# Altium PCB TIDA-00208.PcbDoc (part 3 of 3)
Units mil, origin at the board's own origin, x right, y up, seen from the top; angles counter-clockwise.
Board outline 4724.41 x 3937.01 mil, 4 copper layers (Top Layer, MidLayer1, MidLayer2, Bottom Layer), stack 90 mil thick; 243 components, 132 nets, 667 pads, 234 vias.
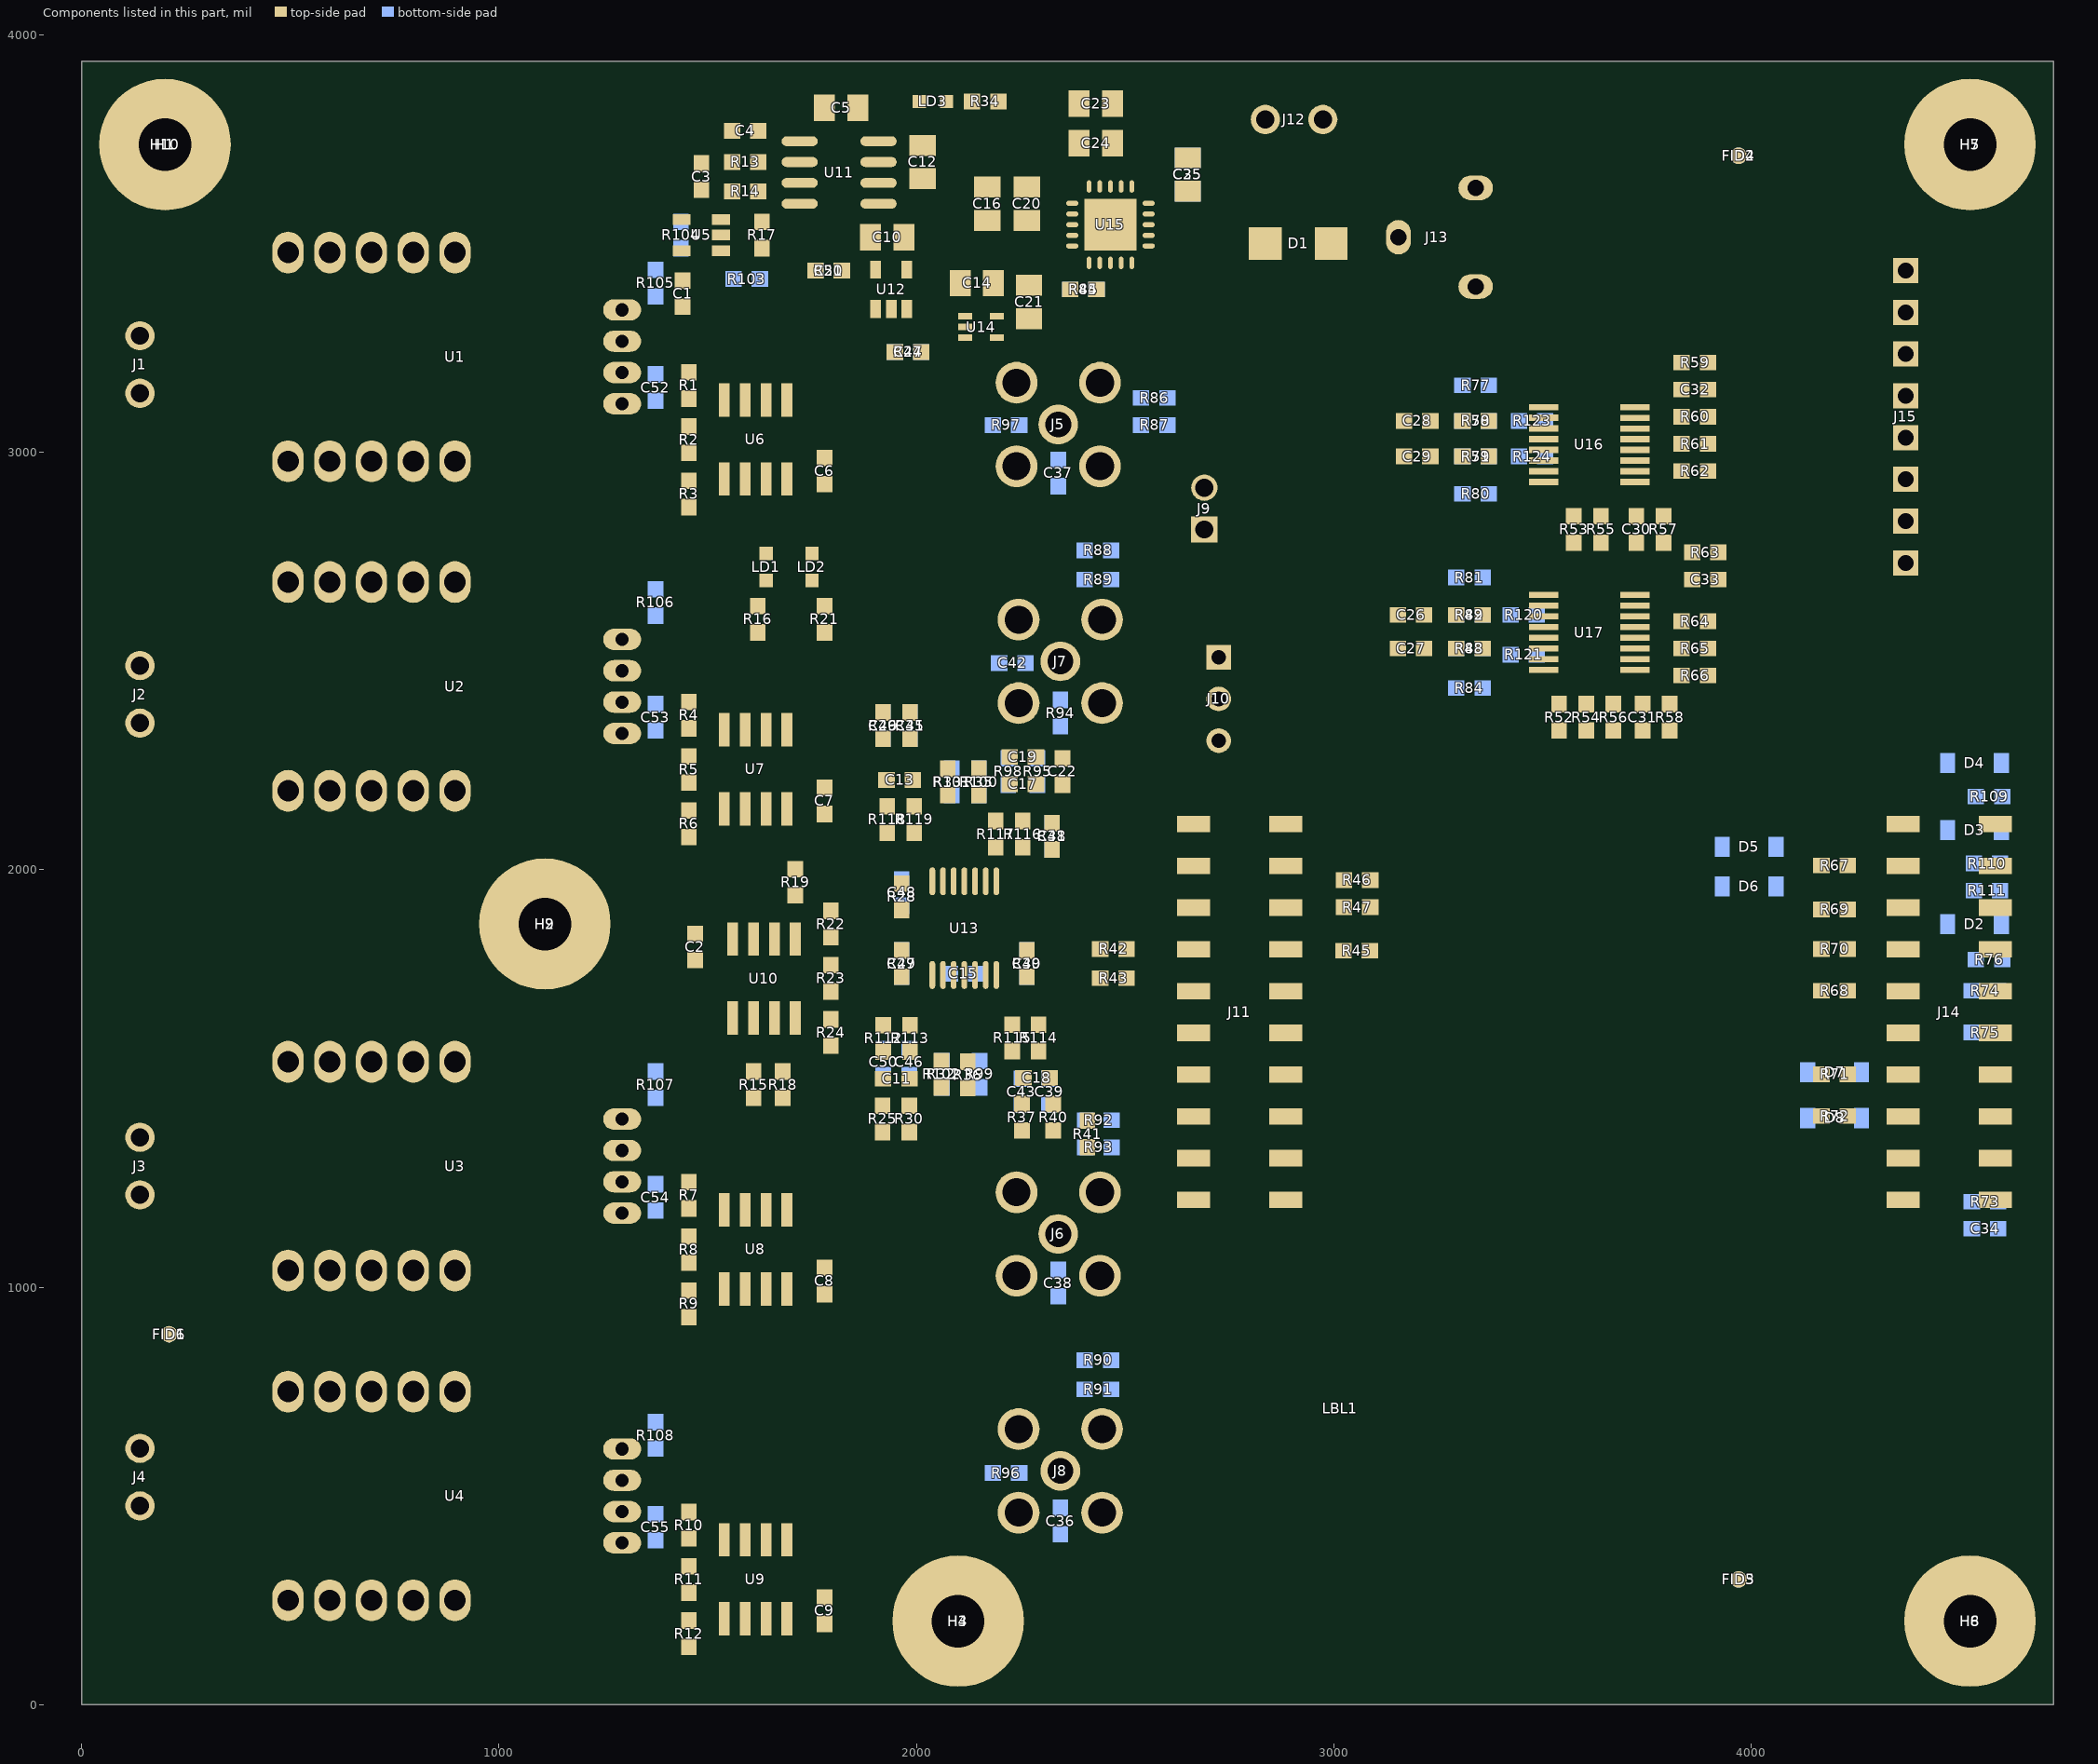
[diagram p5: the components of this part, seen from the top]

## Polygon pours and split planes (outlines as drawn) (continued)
NetJ1_2 on Top Layer "Bottom Layer-No Net" (solid, remove dead copper, pour order 82): 930,2919.37 120,2919.37 80,2959.37 75,2964.37 75,3149.37 75,3152.9 90.55,3168.46 96.47,3174.37 205,3174.37 230,3174.37 290,3114.37 325,3079.37 540,3079.37 910,3079.37 945,3044.37 950,3039.37 950,2954.37 950,2934.37 940,2924.37 935,2919.37 930,2919.37
NetJ1_1 on Top Layer "Bottom Layer-No Net" (solid, remove dead copper, pour order 66): 935,3509.37 935,3444.37 915,3424.37 855,3364.37 670,3364.37 330,3364.37 210,3244.37 205,3239.37 85,3239.37 65,3259.37 65,3309.37 65,3494.37 100,3529.37 105,3534.37 490,3534.37 925,3534.37 930,3529.37 935,3524.37 935,3509.37
NetJ2_1 on Top Layer "Bottom Layer-No Net" (solid, remove dead copper, pour order 70): 935,2720 935,2655 915,2635 855,2575 670,2575 330,2575 210,2455 205,2450 85,2450 65,2470 65,2520 65,2705 100,2740 105,2745 490,2745 925,2745 930,2740 935,2735 935,2720
NetJ2_2 on Top Layer "Bottom Layer-No Net" (solid, remove dead copper, pour order 86): 930,2130 120,2130 80,2170 75,2175 75,2360 75,2363.53 90.55,2379.09 96.47,2385 205,2385 230,2385 290,2325 325,2290 540,2290 910,2290 945,2255 950,2250 950,2165 950,2145 940,2135 935,2130 930,2130
NetD1_2 on Top Layer "Bottom Layer-No Net" (solid, remove dead copper, pour order 87): 3415,3350 2965,3350 2935,3380 2935,3855 2945,3865 3055,3865 3095,3825 3095,3470 3110,3455 3420,3455 3435,3440 3435,3370
NetC25_1 on Top Layer "Bottom Layer-No Net" (solid, remove dead copper, pour order 88): 2875,3410 2875,3615 2840,3650 2600,3650 2570,3680 2520,3680 2515,3675 2515,3630 2545,3630 2555,3620 2556.54,3545 2575,3545 2590,3530 2615,3530 2750,3395 2860,3395
GND on Top Layer "Bottom Layer-No Net" (solid, remove dead copper, pour order 90): 2595,3680 2720,3680 2840,3680 2880,3720 2885,3725 2885,3855 2875,3865 2785,3865 2595,3865 2580,3850 2580,3760 2580,3695 2595,3680
3V3 on Top Layer "Bottom Layer-No Net" (solid, remove dead copper, pour order 93): 2190,3350 2390,3350 2410,3330 2410,3265 2400,3255 2275,3255 2220,3310 2190,3310 2188.8,3311.2 2188.8,3348.8
AVDD on Top Layer "Bottom Layer-No Net" (solid, remove dead copper, pour order 91): 2330,3590 2310,3610 2100,3610 2085,3595 2085,3505 2135,3455 2135,3325 1965,3325 1965,3460 1945,3480 1945,3535 1975,3565 1975,3621 1970,3630 1880,3630 1880,3660 1960,3660 1985,3685 2075,3685 2085,3695 2085,3775 2090,3780 2165,3780 2185,3800 2185,3865 2195,3875 2410,3875 2415,3870 2415,3680 2385,3650 2385,3590
GND on Bottom Layer "Bottom Layer-No Net" (solid, remove dead copper, pour order 53): 3965,1925 3965,2070 3950,2085 3780,2085 3765,2070 3765,1925 3772,1918 3958,1918
GND on Bottom Layer "Bottom Layer-No Net 1" (solid, pour order 50): 4346,2331 4309,2294 4309,1911 4380,1840 4487,1840 4492,1845 4492,1895 4485,1902 4463,1902 4440,1925 4440,2041 4460,2061 4485,2061 4493,2069 4493,2121 4487,2127 4459,2127 4436,2150 4436,2202 4457,2223 4486,2223 4494,2231 4494,2305 4468,2331
GND on Bottom Layer "Bottom Layer-No Net" (solid, remove dead copper, pour order 59): 2360,3475 2520,3475 2535,3490 2535,3605 2610,3680 2610,3865 2375,3865 2360,3850
NetJ4_2 on Bottom Layer "Bottom Layer-No Net" (solid, remove dead copper, pour order 76): 120,191.02 75,236.02 75,450 75,500 90,515 185,515 350,350 910,351.02 950,311.02 950,206.02 935,191.02
NetJ4_1 on Bottom Layer "Bottom Layer-No Net" (solid, remove dead copper, pour order 48): 935,685 920,670 380,670 290,580 75,580 65,590 65,766.02 105,806.02 925,806.02 935,796.02
GND on Bottom Layer "Bottom Layer-No Net" (solid, remove dead copper, pour order 89): 2595,3680 2720,3680 2840,3680 2880,3720 2885,3725 2885,3855 2875,3865 2785,3865 2595,3865 2580,3850 2580,3760 2580,3695 2595,3680
NetJ3_2 on Bottom Layer "Bottom Layer-No Net" (solid, remove dead copper, pour order 73): 120,981.02 75,1026.02 75,1240 95,1260 210,1260 325,1141.02 910,1141.02 950,1101.02 950,996.02 935,981.02
NetJ3_1 on Bottom Layer "Bottom Layer-No Net" (solid, remove dead copper, pour order 61): 935,1506.02 855,1426.02 330,1426.02 225,1320 85,1320 65,1340 65,1556.02 105,1596.02 925,1596.02 935,1586.02
NetJ1_2 on Bottom Layer "Bottom Layer-No Net" (solid, remove dead copper, pour order 81): 930,2919.37 120,2919.37 80,2959.37 75,2964.37 75,3149.37 75,3152.9 90.55,3168.46 96.47,3174.37 205,3174.37 230,3174.37 290,3114.37 325,3079.37 540,3079.37 910,3079.37 945,3044.37 950,3039.37 950,2954.37 950,2934.37 940,2924.37 935,2919.37 930,2919.37
NetJ1_1 on Bottom Layer "Bottom Layer-No Net" (solid, remove dead copper, pour order 65): 935,3509.37 935,3444.37 915,3424.37 855,3364.37 670,3364.37 330,3364.37 210,3244.37 205,3239.37 85,3239.37 65,3259.37 65,3309.37 65,3494.37 100,3529.37 105,3534.37 490,3534.37 925,3534.37 930,3529.37 935,3524.37 935,3509.37
NetJ2_1 on Bottom Layer "Bottom Layer-No Net" (solid, remove dead copper, pour order 69): 935,2720 935,2655 915,2635 855,2575 670,2575 330,2575 210,2455 205,2450 85,2450 65,2470 65,2520 65,2705 100,2740 105,2745 490,2745 925,2745 930,2740 935,2735 935,2720
NetJ2_2 on Bottom Layer "Bottom Layer-No Net" (solid, remove dead copper, pour order 85): 930,2130 120,2130 80,2170 75,2175 75,2360 75,2363.53 90.55,2379.09 96.47,2385 205,2385 230,2385 290,2325 325,2290 540,2290 910,2290 945,2255 950,2250 950,2165 950,2145 940,2135 935,2130 930,2130
GND on Bottom Layer "Bottom Layer-No Net" (solid, remove dead copper, pour order 55): 4240,1570 4240,1310 4240,1255 4255,1240 4335,1240 4340,1240 4350,1250 4355,1255 4355,1445 4355,1560 4340,1575 4330,1585 4260,1585 4255,1585 4240,1570
NetJ4_2 on MidLayer1 "Bottom Layer-No Net" (solid, remove dead copper, pour order 75): 120,191.02 75,236.02 75,450 75,500 90,515 185,515 350,350 910,351.02 950,311.02 950,206.02 935,191.02
NetJ4_1 on MidLayer1 "Bottom Layer-No Net" (solid, remove dead copper, pour order 52): 935,685 920,670 380,670 290,580 75,580 65,590 65,766.02 105,806.02 925,806.02 935,796.02
NetJ3_2 on MidLayer1 "Bottom Layer-No Net" (solid, remove dead copper, pour order 72): 120,981.02 75,1026.02 75,1240 95,1260 210,1260 325,1141.02 910,1141.02 950,1101.02 950,996.02 935,981.02
NetJ3_1 on MidLayer1 "Bottom Layer-No Net" (solid, remove dead copper, pour order 58): 935,1506.02 855,1426.02 330,1426.02 225,1320 85,1320 65,1340 65,1556.02 105,1596.02 925,1596.02 935,1586.02
NetJ1_2 on MidLayer1 "Bottom Layer-No Net" (solid, remove dead copper, pour order 80): 930,2919.37 120,2919.37 80,2959.37 75,2964.37 75,3149.37 75,3152.9 90.55,3168.46 96.47,3174.37 205,3174.37 230,3174.37 290,3114.37 325,3079.37 540,3079.37 910,3079.37 945,3044.37 950,3039.37 950,2954.37 950,2934.37 940,2924.37 935,2919.37 930,2919.37
NetJ1_1 on MidLayer1 "Bottom Layer-No Net" (solid, remove dead copper, pour order 64): 935,3509.37 935,3444.37 915,3424.37 855,3364.37 670,3364.37 330,3364.37 210,3244.37 205,3239.37 85,3239.37 65,3259.37 65,3309.37 65,3494.37 100,3529.37 105,3534.37 490,3534.37 925,3534.37 930,3529.37 935,3524.37 935,3509.37
NetJ2_1 on MidLayer1 "Bottom Layer-No Net" (solid, remove dead copper, pour order 68): 935,2720 935,2655 915,2635 855,2575 670,2575 330,2575 210,2455 205,2450 85,2450 65,2470 65,2520 65,2705 100,2740 105,2745 490,2745 925,2745 930,2740 935,2735 935,2720
NetJ2_2 on MidLayer1 "Bottom Layer-No Net" (solid, remove dead copper, pour order 84): 930,2130 120,2130 80,2170 75,2175 75,2360 75,2363.53 90.55,2379.09 96.47,2385 205,2385 230,2385 290,2325 325,2290 540,2290 910,2290 945,2255 950,2250 950,2165 950,2145 940,2135 935,2130 930,2130
GND on MidLayer1 "MidLayer1-GND" (solid, remove dead copper, pour order 92): 1250,55 1250,3855 1276.89,3881.89 4660,3881.89 4680,3855 4680,75 4670,55.12 4479.88,55
NetJ4_2 on MidLayer2 "Bottom Layer-No Net" (solid, remove dead copper, pour order 74): 120,191.02 75,236.02 75,450 75,500 90,515 185,515 350,350 910,351.02 950,311.02 950,206.02 935,191.02
NetJ4_1 on MidLayer2 "Bottom Layer-No Net" (solid, remove dead copper, pour order 51): 935,685 920,670 380,670 290,580 75,580 65,590 65,766.02 105,806.02 925,806.02 935,796.02
NetJ3_2 on MidLayer2 "Bottom Layer-No Net" (solid, remove dead copper, pour order 71): 120,981.02 75,1026.02 75,1240 95,1260 210,1260 325,1141.02 910,1141.02 950,1101.02 950,996.02 935,981.02
NetJ3_1 on MidLayer2 "Bottom Layer-No Net" (solid, remove dead copper, pour order 57): 935,1506.02 855,1426.02 330,1426.02 225,1320 85,1320 65,1340 65,1556.02 105,1596.02 925,1596.02 935,1586.02
NetJ1_2 on MidLayer2 "Bottom Layer-No Net" (solid, remove dead copper, pour order 79): 930,2919.37 120,2919.37 80,2959.37 75,2964.37 75,3149.37 75,3152.9 90.55,3168.46 96.47,3174.37 205,3174.37 230,3174.37 290,3114.37 325,3079.37 540,3079.37 910,3079.37 945,3044.37 950,3039.37 950,2954.37 950,2934.37 940,2924.37 935,2919.37 930,2919.37
NetJ1_1 on MidLayer2 "Bottom Layer-No Net" (solid, remove dead copper, pour order 63): 935,3509.37 935,3444.37 915,3424.37 855,3364.37 670,3364.37 330,3364.37 210,3244.37 205,3239.37 85,3239.37 65,3259.37 65,3309.37 65,3494.37 100,3529.37 105,3534.37 490,3534.37 925,3534.37 930,3529.37 935,3524.37 935,3509.37
NetJ2_1 on MidLayer2 "Bottom Layer-No Net" (solid, remove dead copper, pour order 67): 935,2720 935,2655 915,2635 855,2575 670,2575 330,2575 210,2455 205,2450 85,2450 65,2470 65,2520 65,2705 100,2740 105,2745 490,2745 925,2745 930,2740 935,2735 935,2720
NetJ2_2 on MidLayer2 "Bottom Layer-No Net" (solid, remove dead copper, pour order 83): 930,2130 120,2130 80,2170 75,2175 75,2360 75,2363.53 90.55,2379.09 96.47,2385 205,2385 230,2385 290,2325 325,2290 540,2290 910,2290 945,2255 950,2250 950,2165 950,2145 940,2135 935,2130 930,2130
AVDD on MidLayer2 "Bottom Layer-No Net" (solid, remove dead copper, pour order 54): 2660,3875 3240,3295 3720,3295 3920,3495 4665,3495 4685,3475 4685,1065 4670,1050 4525,1050 4515,1070 4515,2030 4175,2370 3890,2370 3860,2400 3860,2610 3895,2645 3895,2860 3820,2935 2975,2935 2810,2770 2640,2770 2625,2785 2625,3285 2540,3370 2135,3370 1905,3140 1905,2745 1800,2640 1530,2640 1500,2610 1500,2535 1525,2510 1895,2510 2015,2630 2015,3045 2195,3225 2470,3225 2505,3190 2490,3025 2485,2930 2485,2515 2555,2445 2750,2445 2765,2460 2795,2460 3045,2710 3635,2710 3685,2660 3685,2260 3730,2215 4050,2215 4325,1935 4325,65 1300,65 1250,65.31 1250,3830 1295,3875
3V3 on MidLayer2 "Bottom Layer-No Net" (solid, remove dead copper, pour order 49): 2540,3355 2605,3290 2605,2745 2620,2730 2840,2730 2975,2865 3840,2865 3875,2830 3875,2655 3840,2620 3840,2360 3870,2330 4150,2330 4445,2035 4445,1260 4475,1230 4475,1105 4465,1095 4395,1095 4365,1125 4365,1935 4065,2235 3745,2235 3702.63,2277.37 3702.63,2672.37 3655,2720 3040,2720 2800,2480 2565,2480 2515,2530 2515,3200 2465,3250 2205,3250 2005,3050 2005,2650 1895,2540 1545,2540 1535,2550 1535,2610 1545,2620 1830,2620 1915,2705 1915,3110 2160,3355

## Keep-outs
Keep-Out Layer:
  circle w8: c200,3737.01 r178
  circle w8: c4524.41,3737.01 r178
  circle w8: c4524.41,200 r178
  circle w8: c2100,200 r178
  circle w8: c1110,1870.08 r190.6
  lines w4: 55.12,55.12 55.12,3881.89 4687.2,3881.89 4687.2,55.12 55.12,55.12
  text ".Layer_Name" at 372.2,-1342.12 h60

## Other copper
Top Layer:
  region net AVDD: 2415,3710 2365,3710 2360,3705 2360,3610 2370,3600 2370.49,3600.49 2380,3600.49 2380,3620 2390,3630 2415,3630
  region net NetC25_1: 2519.51,3664.51 2515,3660 2515,3630 2570,3630 2575,3635 2575,3660 2585,3664.51
  text "1" at 3561,89 h100
  text ".Layer_Name" at 372.2,-1342.12 h60
MidLayer1:
  pour cut-out: 1336.81,3386.54 1355,3368.35 1355,3243.35 1340,3228.35 1245,3228.35 1230,3243.35 1230,3383.35 1235,3388.35 1236.81,3386.54
  pour cut-out: 1240,3153.35 1345,3153.35 1360,3138.35 1360,3083.35 1350,3073.35 1240,3073.35 1235,3078.35 1235,3148.35
  pour cut-out: 1336.81,2597.17 1355,2578.98 1355,2453.98 1340,2438.98 1245,2438.98 1230,2453.98 1230,2593.98 1235,2598.98 1236.81,2597.17
  pour cut-out: 1240,2363.98 1345,2363.98 1360,2348.98 1360,2293.98 1350,2283.98 1240,2283.98 1235,2288.98 1235,2358.98
  pour cut-out: 1336.81,1448.19 1355,1430 1355,1305 1340,1290 1245,1290 1230,1305 1230,1445 1235,1450 1236.81,1448.19
  pour cut-out: 1240,1215 1345,1215 1360,1200 1360,1145 1350,1135 1240,1135 1235,1140 1235,1210
  pour cut-out: 1240,425 1345,425 1360,410 1360,355 1350,345 1240,345 1235,350 1235,420
  pour cut-out: 1336.81,658.19 1355,640 1355,515 1340,500 1245,500 1230,515 1230,655 1235,660 1236.81,658.19
  pour cut-out: 3500,65.31 3965,65.31 3965,185 3950,200 3510,200 3500,190
  text "2" at 3659,89 h100
  text ".Layer_Name" at 380,-1340 h60
MidLayer2:
  pour cut-out: 1250,646.38 1344.64,646.38 1355,636.02 1355,441.02 1335,421.02 1250,421.02 1245,426.02 1245,641.38
  pour cut-out: 1250,1436.38 1344.64,1436.38 1355,1426.02 1355,1231.02 1335,1211.02 1250,1211.02 1245,1216.02 1245,1431.38
  pour cut-out: 1250,3374.73 1344.64,3374.73 1355,3364.37 1355,3169.37 1335,3149.37 1250,3149.37 1245,3154.37 1245,3369.73
  pour cut-out: 1250,2585.36 1344.64,2585.36 1355,2575 1355,2380 1335,2360 1250,2360 1245,2365 1245,2580.36
  pour cut-out: 3500,65.31 3965,65.31 3965,185 3950,200 3510,200 3500,190
  text "3" at 3759,89 h100
  text ".Layer_Name" at 380,-1340 h60
Bottom Layer:
  text "4" at 3903,89 h100
  text ".Layer_Name" at 372.2,-1342.12 h60

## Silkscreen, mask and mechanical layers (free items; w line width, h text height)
Top Overlay:
  circle w8: c2330,3610 r10
  circle w8: c2076.37,3327 r10.63
  circle w8: c1901.19,3292.77 r10.63
  circle w8: c1982.23,3592.59 r10.63
  circle w8: c1530.83,3441.37 r10.63
  circle w8: c2340,3066.38 r160.34
  circle w8: c2345,2498.98 r159.39
  circle w8: c2340,1127.4 r161.48
  circle w8: c2345,560 r160
  lines w6: 1510,3752 1510,3742 1529.73,3722.27 1530.02,3722.27 ; 1886,1664 1887,1664 1893.8,1657.2 1893.8,1655.98 ; 2024,2126 2033,2126 2043,2116 ; 2133,2321 2138,2316 2138,2272 ; 2217.2,2025.02 2217.2,1964.8 2238,1944 ; 2314.98,2177.8 2314.98,2165.02 2323,2157 2386,2157 ; 2355.2,1466.98 2380.02,1466.98 2388,1459
  lines w7.87: 1383.16,3589 1521.22,3589 1530.02,3597.8 ; 1500,450 1500,151 1521,151 ; 1500,1240 1500,941 1521,941 ; 1500,2390 1500,2091 1521,2091 ; 1500,3180 1500,2881 1521,2881 ; 1560,151 1730,151 1730,450 1561,450 ; 1560,941 1730,941 1730,1240 1561,1240 ; 1560,2091 1730,2091 1730,2390 1561,2390 ; 1560,2881 1730,2881 1730,3180 1561,3180 ; 1689,1590 1520,1590 1520,1889 1690,1889 ; 1729,1889 1750,1889 1750,1590 ; 3295,2781 3306,2770 3535,2770 ; 3450.1,2449.6 3450.1,2688.1 3768,2688.1 3768,2450.2 3450.7,2450.2 ; 3450.1,2899.6 3450.1,3138.1 3767.2,3138.1 3767.2,2899.8 3450.3,2899.8 ; 3535,2770 3534,2770 3525,2761 3525,2780 3535,2770 ; 2609.41,1109.05 2939.41,1109.05 2939.41,2209.05 2609.41,2209.05 2609.41,1109.05 ; 4309.41,1109.05 4639.41,1109.05 4639.41,2209.05 4309.41,2209.05 4309.41,1109.05 ; 4320,2685 4320,3485 4420,3485 4420,2685 4320,2685
  text "+6V" at 3114,3783 h60 r90
  text "GND" at 2736,3779 h60 r90
  text "GND" at 4195,3410 h55
  text "SDI" at 4215,3315 h55
  text "/CS" at 4220,3215 h55
  text "SCLK" at 4180,3125 h55
  text "SDO_B2" at 4115,3020 h55
  text "GND_FLT" at 2710,3005 h55
  text "SDO_A2" at 4110,2915 h55
  text "SDO_B1" at 4120,2815 h55
  text "SDO_A1" at 4115,2705 h55
  text "OC_FLT" at 2720,2675 h55
  text "2" at 4652.2,2125 h55
  text "1" at 4270.2,2104 h55
  text "1" at 2575.35,2093 h55
  text "2" at 2955.35,2093 h55
  text "19" at 4243.2,1186 h55
  text "20" at 2955.35,1184 h55
  text "20" at 4651.2,1159 h55
  text "19" at 2545.35,1144 h55
  text "TIDA-00208" at 2625,215 h150
  text "REV: E2" at 2650,75 h150
  text ".Layer_Name" at 372.2,-1342.12 h60
Bottom Overlay:
  text ".Layer_Name" at 372.2,-1342.12 h60
Top Paste:
  text ".Layer_Name" at 372.2,-1342.12 h60
Bottom Paste:
  text ".Layer_Name" at 372.2,-1342.12 h60
Top Solder:
  text ".Layer_Name" at 372.2,-1342.12 h60
  text ".Layer_Name" at 372.2,-1342.12 h60
Bottom Solder:
  text ".Layer_Name" at 372.2,-1342.12 h60
Drill Guide:
  text ".Layer_Name" at 372.2,-1342.12 h60
M1 Board Outline:
  the board outline again, w10
  text ".layer_Name" at 392,-1342 h60
M2 Board Dimensions:
  rectangle: -80.3,-894.12 294.7,-769.12
  rectangle: -205.3,-769.12 -80.3,-644.12
  lines w7: -205.3,-769.12 794.7,-769.12 ; -80.3,-894.12 -80.3,-644.12 ; 44.7,-894.12 44.7,-644.12 ; 294.7,-894.12 294.7,-644.12 ; 544.7,-894.12 544.7,-644.12 ; -205.3,-894.12 -205.3,-644.12 794.7,-644.12 794.7,-894.12 -205.3,-894.12
  lines w10: -205.3,-959.12 -205.3,-939.12 ; -145.3,-969.12 -205.3,-949.12 ; -145.3,-929.12 -205.3,-949.12 ; 18.78,-949.12 -205.3,-949.12 ; 570.61,-949.12 794.7,-949.12 ; 734.7,-969.12 794.7,-949.12 ; 734.7,-929.12 794.7,-949.12 ; 794.7,-959.12 794.7,-939.12
  text "1000 (mil)" at 28.78,-985.11 h60
M3 3D STEP Top:
  text ".Layer_Name" at 372.2,-1342.12 h60
M4 3D STEP Bottom:
  text ".Layer_Name" at 372.2,-1342.12 h60
M5 Assembly Top:
  circle w6: c1496,3483 r8
  circle w6: c1866.35,3343.16 r8
  circle w6: c2080,3328 r8
  lines w7.87: 1617,2833 1667,2833 ; 1641,2782 1641,2807 ; 1641,2854 1641,2833 ; 1727,2833 1777,2833 ; 1751,2782 1751,2807 ; 1751,2854 1751,2833 ; 2007,3890 2028,3890 ; 2026,3864 2026,3914 ; 2053,3890 2078,3890 ; 1641,2833 1666,2808 1616,2808 1641,2833 ; 1751,2833 1726,2808 1776,2808 1751,2833 ; 2028,3890 2053,3915 2053,3865 2028,3890
  lines w10: -496.8,-1413.79 6103.2,-1413.79 ; -496.8,-1210.46 6105.2,-1210.46 ; -496.8,-1007.12 -496.8,-1617.12 3508.2,-1617.12 6105.2,-1617.12 6105.2,-1007.12 -496.3,-1007.12 -496.3,-1617.12 1079.2,-1617.12 ; 1968.2,-1617.12 1968.2,-1007.12 ; 3235.2,-1210.46 3235.2,-1007.12 ; 4075.2,-1210.46 4075.2,-1007.12 ; 4697.2,-1623.62 4697.2,-1420.79
  text "8" at 4279,3418 h60
  text "14" at 1173,3094 h60
  text "1" at 885,3063 h60
  text "1" at 4285,2707 h60
  text "14" at 1168,2311 h60
  text "1" at 881,2262 h60
  text "14" at 1174,1158 h60
  text "1" at 882,1112 h60
  text "14" at 1172,368 h60
  text "1" at 879,321 h60
  text "COMPONENTS MARKED 'DNP' SHOULD NOT BE POPULATED." at 948.7,-802.12 h60
  text "ASSEMBLY VARIANT:" at 948.2,-917.62 h60
  text ".VariantName" at 1984.2,-917.62 h60
  text "PCB VIEWED FROM TOP SIDE" at -433.3,-1139.29 h60
  text "BOARD #:" at 2043.2,-1139.29 h60
  text ".PRJ_Number" at 2588.7,-1139.29 h60
  text "REV:" at 3433.2,-1139.29 h60
  text ".PCB_Rev" at 3724.7,-1139.29 h60
  text "SVN REV:" at 4271.2,-1139.29 h60
  text ".VersionControl_RevNumber" at 4777.2,-1139.29 h60
  text "IGNORE ->" at -433.3,-1342.12 h60
  text ".layer_Name" at 392,-1342 h60
  text "PLOT NAME =" at -433.3,-1547.96 h60
  text ".plot_File_Name" at 372.2,-1547.96 h60
  text "GENERATED    :" at 2045.2,-1547.96 h60
  text ".Print_Date" at 2914.7,-1547.96 h60
  text ".Print_Time" at 3643.7,-1547.96 h60
  text "TEXAS INSTRUMENTS" at 4908.2,-1547.96 h60
M6 Assembly Bottom:
  lines w10: -497.3,-1210.96 6104.7,-1210.96 ; -495.3,-1414.29 6104.7,-1414.29 ; 910.7,-1624.12 910.7,-1421.29 ; 1532.7,-1210.96 1532.7,-1007.62 ; 2372.7,-1210.96 2372.7,-1007.62 ; 3639.7,-1617.62 3639.7,-1007.62 ; 4528.7,-1617.62 6104.2,-1617.62 6104.2,-1007.62 -497.3,-1007.62 -497.3,-1617.62 2099.7,-1617.62 6104.7,-1617.62 6104.7,-1007.62
  text "COMPONENTS MARKED 'DNP' SHOULD NOT BE POPULATED." at 5897.2,-801.62 h60
  text ".VariantName" at 4853.2,-917.62 h60
  text "ASSEMBLY VARIANT:" at 5892.2,-917.62 h60
  text ".VersionControl_RevNumber" at 830.7,-1139.79 h60
  text "SVN REV:" at 1336.7,-1139.79 h60
  text ".PCB_Rev" at 1883.2,-1139.79 h60
  text "REV:" at 2174.7,-1139.79 h60
  text ".PRJ_Number" at 3019.2,-1139.79 h60
  text "BOARD #:" at 3564.7,-1139.79 h60
  text "PCB VIEWED FROM BOTTOM SIDE" at 6041.2,-1139.79 h60
  text "IGNORE ->" at 2343.05,-1342.12 h60
  text ".layer_Name" at 1266,-1343 h60
  text "TEXAS INSTRUMENTS" at 699.7,-1548.46 h60
  text ".Print_Time" at 1964.2,-1548.46 h60
  text ".Print_Date" at 2693.2,-1548.46 h60
  text "GENERATED    :" at 3562.7,-1548.46 h60
  text ".plot_File_Name" at 5235.7,-1548.46 h60
  text "PLOT NAME =" at 6041.2,-1548.46 h60
M9 Title Sheet:
  drawing of 57 lines, arcs and shapes, not listed
  text "1" at 535.03,7552.88 h70
  text "2" at 3030.7,7552.88 h70
  text "3" at 5520.04,7552.88 h70
  text "4" at 8026.71,7552.88 h70
  text "5" at 10525.7,7552.88 h70
  text "6" at 13030.7,7552.88 h70
  text "A" at -621.3,6409.88 h70
  text "A" at 14178.7,6409.88 h70
  text "B" at -621.3,4029.88 h70
  text "B" at 14178.7,4029.88 h70
  text "C" at -621.3,1654.88 h70
  text "C" at 14178.7,1654.88 h70
  text "PROJECT TITLE" at 11138.7,-206.12 h35
  text ".PRJ_Title" at 11188.7,-339.45 h55
  text "DESIGNED FOR:" at 11138.7,-507.12 h45
  text ".PRJ_Customer" at 11188.7,-647.12 h70
  text "D" at -621.3,-715.12 h70
  text "D" at 14178.7,-715.12 h70
  text "FILE NAME:" at 11138.7,-807.12 h45
  text ".PCB_File_Name_No_Path" at 11188.7,-927.12 h70
  text "Texas Instruments (TI) and/or its licensors do not warrant the accuracy or completeness of this specification" at 6169.2,-1088.96 h45
  text "ENGINEER:" at 11138.7,-1097.12 h45
  text "LAYOUT BY:" at 12643.7,-1097.12 h45
  text "or any information contained therein. TI and/or its licensors do not warrant that this design will meet" at 6124.21,-1201.63 h45
  text ".PRJ_Engineer" at 11188.7,-1252.11 h70
  text ".PCB_Layout" at 12694.2,-1252.11 h70
  text "the specifications, will be suitable for your application or fit for any particular purpose, or will operate in" at 6124.21,-1314.29 h45
  text "ALTIUM DESIGNER VERSION:" at 12643.7,-1407.12 h45
  text "an implementation. TI and/or its licensors do not warrant that the design is production worthy. You should" at 6124.21,-1426.96 h45
  text "completely validate and test your design implementation to confirm the system functionality for your application." at 6169.2,-1539.62 h45
  text ".print_Scale" at 11188.7,-1540.45 h70
  text ".Application_BuildNumber" at 12694.2,-1540.45 h70
  text "1" at 535.03,-1747.12 h70
  text "2" at 3030.7,-1747.12 h70
  text "3" at 5520.04,-1747.12 h70
  text "4" at 8026.71,-1747.12 h70
  text "5" at 10525.7,-1747.12 h70
  text "6" at 13030.7,-1747.12 h70
M10 Fab Notes:
  drawing of 220 lines, arcs and shapes, not listed
  text "DESIGN INFORMATION" at 12176.21,6326.38 h60
  text "(REFER ALSO ARRAY/PANEL PROFILING INFORMATION)" at 11814.66,6164.66 h60
  text "BOARD SIZE" at 11128.66,6160.38 h60
  text "120 MM" at 11590.98,6032.56 h60
  text "X" at 12096.66,6032.56 h60
  text "100 MM" at 12327.98,6032.56 h60
  text "Number of Layers :" at 11531.66,5835.38 h60
  text "4" at 12626.47,5825.38 h60
  text "MIN. TRACK WIDTH:" at 11531.66,5696.38 h60
  text "8" at 12627.9,5696.38 h60
  text "MIL" at 12782.66,5696.38 h60
  text "8" at 12635,5565 h60
  text "MIN. CLEARANCE:" at 11531.66,5564.38 h60
  text "MIL" at 12782.66,5564.38 h60
  text "MIN. VIA PAD SIZE:" at 11531.66,5432.38 h60
  text "26" at 12597.91,5432.38 h60
  text "MIL" at 12782.66,5432.38 h60
  text "0.177mm (7MIL)" at 12226.66,5290.67 h60
  text "MINIMUM ANNULAR RING" at 11202.42,5286.38 h60
  text "EXTERNAL" at 12934.66,5286.38 h60
  text "PER" at 11402.42,5168.38 h60
  text "IPC-D-275 CLASS 2 LEVEL C" at 11622.42,5168.38 h60
  text "MIL, HOLES" at 13110.66,5056.09 h60
  text "+/-" at 12718.2,5055.38 h60
  text "+/-" at 13572.2,5055.38 h60
  text "REGISTRATION TOLERANCES:" at 11202.42,5050.38 h60
  text "METAL" at 12402.2,5050.38 h60
  text "5" at 12978.4,5050.38 h60
  text "3" at 13811.4,5050.38 h60
  text "MIL" at 13927.66,5050.38 h60
  text "MATERIAL:" at 11127.66,4840.92 h60
  text "FR-4 High Tg" at 12114.1,4700.59 h60
  text "X" at 11400.66,4697.02 h60
  text "FR-408" at 11548.66,4692.02 h60
  text "OTHER" at 13036.66,4692.02 h60
  text "63 MIL (1.6mm) +/-10%" at 11868.76,4529.3 h60
  text "THICKNESS:" at 11202.42,4525.02 h60
  text "X" at 11740.59,4525.02 h60
  text "OTHER" at 13153.66,4525.02 h60
  text "TOLERANCE:" at 11202.42,4367.02 h60
  text "X" at 12041.73,4367.02 h60
  text "ANSI IPC-6012 TYPE 3 CLASS 2" at 12228.67,4367.02 h60
  text "OTHER +/-" at 12228.66,4211.02 h60
  text "BOW & TWIST:" at 11202.42,4054.02 h60
  text "X" at 12041.73,4054.02 h60
  text "ANSI IPC-6012 TYPE 3 CLASS 2" at 12228.67,4054.02 h60
  text "OTHER +/-" at 12228.66,3895.51 h60
  text "COPPER THICKNESS (FINISHED):" at 11127.66,3760.02 h60
  text "1.4MIL (1oz)" at 12007.66,3607.3 h60
  text "2MIL (1.4oz)" at 12774.66,3607.3 h60
  text "2.8MIL (2oz)" at 13501.66,3607.3 h60
  text "OUTER:" at 11484.66,3603.02 h60
  text "X" at 11879.2,3602.38 h60
  text "1.4MIL (1oz)" at 12007.66,3450.3 h60
  text "2.8MIL (2oz)" at 12774.66,3450.3 h60
  text "N/A" at 13501.2,3450.66 h60
  text "INNER SIGNAL:" at 11195.58,3446.02 h60
  text "X" at 11880.62,3446.02 h60
  text "DRILLING:" at 11127.66,3307.02 h60
  text "REFERENCE:" at 11202.42,3190.02 h60
  text "X" at 11850.66,3190.02 h60
  text "AS SHOWN" at 12037.66,3190.02 h60
  text "X" at 12751.66,3190.02 h60
  text "NC_DRILL FILES" at 12888.66,3190.02 h60
  text "PTH MIN COPPER THICKNESS:" at 11202.42,3032.02 h60
  text "X" at 12552.66,3032.02 h60
  text "1MIL" at 12689.66,3032.02 h60
  text "OTHER" at 13186.66,3032.02 h60
  text "BOARD FINISH:" at 11127.66,2873.02 h60
  text "SILKSCREEN:" at 11282.88,2755.02 h60
  text "X" at 12231.66,2755.02 h60
  text "TOP" at 12357.66,2755.02 h60
  text "X" at 12741.66,2755.02 h60
  text "BOTTOM" at 12868.66,2755.02 h60
  text "SILKSCREEN COLOR:" at 11282.88,2588.02 h60
  text "X" at 12230.62,2588.02 h60
  text "WHITE" at 12357.66,2588.02 h60
  text "OTHER" at 12868.66,2588.02 h60
  text "SOLDER RESIST COLOR:" at 11282.88,2418.02 h60
  text "X" at 11850.62,2258.82 h60
  text "GREEN" at 11977.66,2258.82 h60
  text "BLUE" at 12568.66,2258.82 h60
  text "OTHER" at 13106.66,2258.82 h60
  text "IMMERSION GOLD (ENIG)" at 12188.66,2070.3 h60
  text "ENEPIG" at 13526.2,2067.02 h60
  text "SURFACE FINISH:" at 11127.66,2066.02 h60
  text "X" at 12001.71,2066.02 h60
  text "IMM. TIN/SILVER OR EQUIV" at 11457.2,1909.02 h60
  text "OTHER" at 12888.66,1909.02 h60
  text "ARRAY/PANEL:" at 11127.66,1730.02 h60
  text "CUT AND TRIM PER MECH LAYER 1" at 12188.66,1725.73 h60
  text "N.C. ROUTE" at 12188.66,1574.02 h60
  text "X" at 12867.66,1574.02 h60
  text "V. SCORE" at 13054.66,1574.02 h60
  text "CERTIFICATION:" at 11127.66,1437.02 h60
  text "MATERIALS AND WORKMANSHIP FOR ALL PCBS" at 11852.66,1437.02 h60
  text "TO MEET OR EXCEED THE REQUIREMENTS OF:" at 11852.66,1339.02 h60
  text "X" at 11479.16,1202.51 h60
  text "ANSI IPC-A-600F CLASS ->" at 11618.16,1202.51 h60
  text "X" at 13257.21,1202.51 h60
  text "2" at 13376.16,1202.51 h60
  text "1" at 13061.16,1201.02 h60
  text "3" at 13730.16,1201.02 h60
  text "X" at 11481.21,1043.02 h60
  text "UL 94V-0" at 11618.16,1043.02 h60
  text "X" at 12293.21,1043.02 h60
  text "RoHS" at 12430.16,1043.02 h60
  text "OTHER" at 13074.56,1043.02 h60
  text "PER ORDER" at 13471.62,1043.02 h60
  text "ADDITIONAL REQUIREMENTS:" at 11127.66,902.02 h60
  text "VIA TENTING:" at 12602.2,806.38 h60
  text "X" at 13390.49,806.49 h60
  text "YES" at 13173.87,797.3 h60
  text "NO" at 13568.67,797.07 h60
  text "MICROSECTION:" at 11202.42,787.02 h60
  text "YES" at 12108.16,787.02 h60
  text "REQUIRED" at 12969.66,630.87 h60
  text "BARE BOARD ELEC. TEST:" at 11202.42,628.02 h60
  text "NONE" at 12508.16,628.02 h60
  text "X" at 12842.66,628.02 h60
  text "PER ORDER" at 13561.66,628.02 h60
  text "MANUFACTURER'S UL:" at 11202.42,471.02 h60
  text "RAIL" at 12368.16,466.73 h60
  text "METAL" at 12859.97,466.73 h60
  text "X" at 13235.2,466.38 h60
  text "SILK" at 13371.66,466.73 h60
M11 Gerber Information:
  lines w10: -496.8,-1413.79 6103.2,-1413.79 ; -496.8,-1210.46 6105.2,-1210.46 ; -496.8,-1007.12 -496.8,-1617.12 3508.2,-1617.12 6105.2,-1617.12 6105.2,-1007.12 -496.3,-1007.12 -496.3,-1617.12 1079.2,-1617.12 ; 1968.2,-1617.12 1968.2,-1007.12 ; 3235.2,-1210.46 3235.2,-1007.12 ; 4075.2,-1210.46 4075.2,-1007.12 ; 4697.2,-1623.62 4697.2,-1420.79
  text "ALL ARTWORK VIEWED FROM TOP SIDE" at -433.3,-1139.29 h60
  text "BOARD #:" at 2043.2,-1139.29 h60
  text ".PRJ_Number" at 2588.7,-1139.29 h60
  text "REV:" at 3433.2,-1139.29 h60
  text ".PCB_Rev" at 3724.7,-1139.29 h60
  text "SVN REV:" at 4271.2,-1139.29 h60
  text ".VersionControl_RevNumber" at 4777.2,-1139.29 h60
  text "LAYER NAME =" at -433.3,-1342.12 h60
  text "PLOT NAME =" at -433.3,-1547.96 h60
  text ".plot_File_Name" at 372.2,-1547.96 h60
  text "GENERATED    :" at 2045.2,-1547.96 h60
  text ".Print_Date" at 2914.7,-1547.96 h60
  text ".Print_Time" at 3643.7,-1547.96 h60
  text "TEXAS INSTRUMENTS" at 4908.2,-1547.96 h60
M12 Stackup:
  lines w6: 11093,7194.5 13994,7194.5 ; 11093,7303 13994,7303 ; 11033,6511 ccw(c11068,6511) 11068,6476 14019,6476 ccw(c14019,6511) 14054,6511 14054,7395 ccw(c14019,7395) 14019,7430 11068,7430 ccw(c11068,7395) 11033,7395 11033,6511
  text "Layer Stack Up Detail for: TIDA-00208.PcbDoc" at 11093,7331.1 h48
  text "Layer" at 11093,7262.5 h25
  text "Gerber" at 12106.81,7262.5 h25
  text "Copper" at 12781.59,7262.5 h25
  text "Dielectric" at 13497.19,7262.5 h25
  text "Name" at 11093,7212.5 h25
  text "Document" at 12106.81,7212.5 h25
  text "Thickness" at 12781.59,7212.5 h25
  text "Material" at 13497.19,7212.5 h25
  text "Top Solder Mask" at 11093,7141.81 h35
  text "(.GTS)" at 12106.81,7141.81 h35
  text "Solder Resist" at 13497.19,7141.81 h35
  text "Top Layer" at 11093,7042.44 h35
  text "(.GTL)" at 12106.81,7042.44 h35
  text "1.4mil" at 12781.59,7042.44 h35
  text "FR-4" at 13497.19,6992.75 h35
  text "L2_GND-PLANE" at 11093,6943.06 h35
  text "(.G1)" at 12106.81,6943.06 h35
  text "1.4mil" at 12781.59,6943.06 h35
  text "FR-4" at 13497.19,6893.38 h35
  text "L3_PWR-PLANE" at 11093,6843.69 h35
  text "(.G2)" at 12106.81,6843.69 h35
  text "1.4mil" at 12781.59,6843.69 h35
  text "FR-4" at 13497.19,6794 h35
  text "Bottom Layer" at 11093,6744.31 h35
  text "(.GBL)" at 12106.81,6744.31 h35
  text "1.4mil" at 12781.59,6744.31 h35
  text "Bottom Solder Mask" at 11093,6644.94 h35
  text "(.GBS)" at 12106.81,6644.94 h35
  text "Solder Resist" at 13497.19,6644.94 h35
  text "THIS IS NOT AN IMPEDANCE CONTROLLED BOARD" at 11621,6520 h35
M13 Component Bodies Top:
  text ".Layer_Name" at 372.2,-1342.12 h60
M14 Component Bodies Bottom:
  text ".Layer_Name" at 372.2,-1342.12 h60
M15 Courtyards Top:
  text ".Layer_Name" at 372.2,-1342.12 h60
M16 Courtyards Bottom:
  text ".Layer_Name" at 372.2,-1342.12 h60
Drill Drawing:
  text ".legend" at 2806.3,4896.38 h60
  text "Drill Table" at 2935,4760 h60
  text "TOLERANCE FOR PTH EXCEPT 12 MILS AND 16 MILS+/- 3MIL" at 2815,4610 h60
  text "TOLERANCE FOR PTH  SLOT +/- 3MIL" at 2815,4525 h60
  text "TOLERANCE FOR 16MIL DRILL +0/-16MIL" at 2820,4430 h60
  text "TOLERANCE FOR 12MIL DRILL +0/-12MIL" at 2820,4340 h60
  text ".Layer_Name" at 372.2,-1342.12 h60

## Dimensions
0,0 to 0,3937.01 on Drill Drawing
4724.41,0 to 0,0 on Drill Drawing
